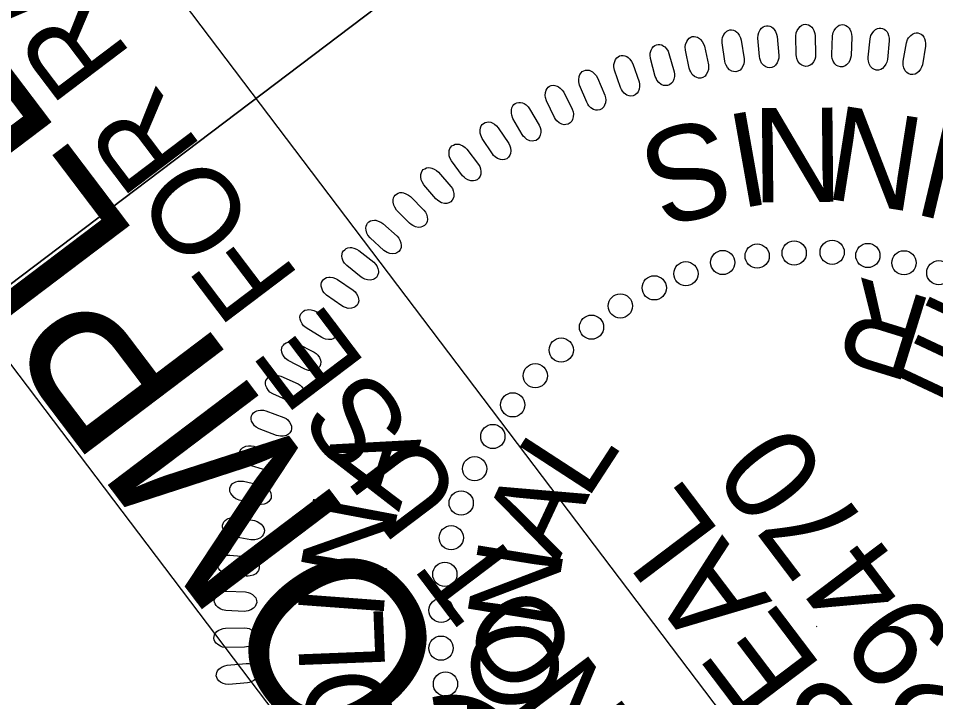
# Model space of a CAD drawing. Extents: x 475599 to 477488, y 499839 to 501843.
# Drawn here: x 475746.4 to 475807, y 501118.9 to 501163.8 of the extents above; entities that cross this region are included whole.
import ezdxf

# ---------------------------------------------------------------- set-up
doc = ezdxf.new("R2010")
doc.units = 0
for name, color, linetype in [('Sheet PE Seal Cell', 7, 'Continuous'), ('Sheet Plan CELL', 7, 'Continuous'), ('Sheet Sticker Exception Certification CELL', 7, 'Continuous'), ('Sheet Sticker Incomplete CELL', 7, 'Continuous')]:
    doc.layers.add(name, color=color, linetype=linetype)

msp = doc.modelspace()

# ---------------------------------------------------------------- linework, layer by layer
at = {"layer": 'Sheet PE Seal Cell'}
msp.add_line((475799.157, 501123.615), (475799.194, 501123.643), dxfattribs=at)
for points in [[(475795.387, 501161.299), (475795.286, 501162.522), (475795.305, 501162.744), (475795.345, 501162.887), (475795.443, 501163.065), (475795.531, 501163.183), (475795.637, 501163.272), (475795.738, 501163.319), (475795.848, 501163.348), (475795.961, 501163.338), (475796.083, 501163.318), (475796.192, 501163.267), (475796.304, 501163.176), (475796.371, 501163.102), (475796.45, 501162.957), (475796.524, 501162.784), (475796.56, 501162.627), (475796.67, 501161.375), (475796.661, 501161.204), (475796.628, 501161.061), (475796.552, 501160.895), (475796.452, 501160.746), (475796.362, 501160.659), (475796.21, 501160.587), (475796.062, 501160.554), (475795.911, 501160.582), (475795.802, 501160.623), (475795.667, 501160.712), (475795.534, 501160.871), (475795.452, 501161.045), (475795.412, 501161.171)], [(475797.815, 501161.431), (475797.791, 501162.657), (475797.825, 501162.877), (475797.874, 501163.018), (475797.983, 501163.19), (475798.078, 501163.301), (475798.189, 501163.384), (475798.292, 501163.425), (475798.404, 501163.447), (475798.516, 501163.429), (475798.637, 501163.402), (475798.742, 501163.345), (475798.848, 501163.246), (475798.91, 501163.168), (475798.981, 501163.019), (475799.044, 501162.841), (475799.07, 501162.682), (475799.101, 501161.426), (475799.082, 501161.256), (475799.039, 501161.116), (475798.953, 501160.954), (475798.844, 501160.812), (475798.748, 501160.731), (475798.592, 501160.668), (475798.443, 501160.645), (475798.293, 501160.682), (475798.187, 501160.73), (475798.058, 501160.827), (475797.935, 501160.994), (475797.865, 501161.173), (475797.833, 501161.301)], [(475800.162, 501161.446), (475800.216, 501162.671), (475800.262, 501162.888), (475800.32, 501163.026), (475800.44, 501163.191), (475800.542, 501163.296), (475800.658, 501163.371), (475800.764, 501163.406), (475800.877, 501163.421), (475800.987, 501163.396), (475801.106, 501163.361), (475801.208, 501163.297), (475801.308, 501163.192), (475801.364, 501163.11), (475801.425, 501162.958), (475801.477, 501162.776), (475801.492, 501162.616), (475801.445, 501161.36), (475801.415, 501161.191), (475801.364, 501161.054), (475801.268, 501160.899), (475801.15, 501160.764), (475801.049, 501160.688), (475800.89, 501160.635), (475800.739, 501160.623), (475800.592, 501160.669), (475800.49, 501160.723), (475800.367, 501160.828), (475800.255, 501161.002), (475800.195, 501161.185), (475800.171, 501161.315)], [(475802.568, 501161.267), (475802.699, 501162.487), (475802.759, 501162.702), (475802.826, 501162.835), (475802.956, 501162.992), (475803.064, 501163.09), (475803.184, 501163.158), (475803.292, 501163.186), (475803.406, 501163.194), (475803.515, 501163.163), (475803.631, 501163.119), (475803.728, 501163.05), (475803.822, 501162.939), (475803.873, 501162.854), (475803.924, 501162.697), (475803.964, 501162.513), (475803.97, 501162.352), (475803.844, 501161.102), (475803.803, 501160.935), (475803.743, 501160.801), (475803.638, 501160.652), (475803.512, 501160.525), (475803.406, 501160.456), (475803.244, 501160.413), (475803.093, 501160.41), (475802.949, 501160.465), (475802.85, 501160.526), (475802.734, 501160.638), (475802.634, 501160.819), (475802.585, 501161.006), (475802.569, 501161.137)], [(475790.751, 501160.531), (475790.498, 501161.732), (475790.49, 501161.954), (475790.511, 501162.101), (475790.586, 501162.291), (475790.659, 501162.418), (475790.752, 501162.519), (475790.846, 501162.58), (475790.952, 501162.622), (475791.065, 501162.626), (475791.189, 501162.621), (475791.303, 501162.585), (475791.426, 501162.508), (475791.501, 501162.443), (475791.598, 501162.31), (475791.693, 501162.147), (475791.748, 501161.995), (475792.015, 501160.767), (475792.028, 501160.597), (475792.013, 501160.451), (475791.958, 501160.276), (475791.877, 501160.117), (475791.799, 501160.019), (475791.657, 501159.928), (475791.515, 501159.877), (475791.361, 501159.885), (475791.248, 501159.913), (475791.103, 501159.984), (475790.951, 501160.125), (475790.848, 501160.287), (475790.792, 501160.407)], [(475793.096, 501160.991), (475792.919, 501162.205), (475792.925, 501162.427), (475792.956, 501162.574), (475793.042, 501162.758), (475793.123, 501162.88), (475793.222, 501162.975), (475793.32, 501163.03), (475793.428, 501163.066), (475793.542, 501163.063), (475793.665, 501163.05), (475793.776, 501163.006), (475793.895, 501162.922), (475793.965, 501162.852), (475794.054, 501162.714), (475794.138, 501162.544), (475794.184, 501162.391), (475794.373, 501161.148), (475794.375, 501160.977), (475794.351, 501160.832), (475794.285, 501160.662), (475794.195, 501160.507), (475794.11, 501160.414), (475793.964, 501160.332), (475793.818, 501160.291), (475793.664, 501160.309), (475793.554, 501160.343), (475793.413, 501160.423), (475793.271, 501160.573), (475793.178, 501160.742), (475793.13, 501160.865)], [(475804.892, 501161.004), (475805.099, 501162.214), (475805.172, 501162.424), (475805.248, 501162.553), (475805.386, 501162.701), (475805.501, 501162.793), (475805.625, 501162.852), (475805.735, 501162.874), (475805.849, 501162.875), (475805.956, 501162.836), (475806.068, 501162.787), (475806.162, 501162.711), (475806.248, 501162.594), (475806.294, 501162.505), (475806.335, 501162.347), (475806.364, 501162.159), (475806.359, 501161.999), (475806.154, 501160.759), (475806.104, 501160.595), (475806.035, 501160.465), (475805.921, 501160.323), (475805.787, 501160.204), (475805.677, 501160.142), (475805.513, 501160.109), (475805.362, 501160.115), (475805.222, 501160.18), (475805.127, 501160.246), (475805.018, 501160.366), (475804.929, 501160.553), (475804.892, 501160.742), (475804.885, 501160.874)], [(475788.506, 501159.989), (475788.178, 501161.171), (475788.156, 501161.392), (475788.168, 501161.541), (475788.231, 501161.734), (475788.296, 501161.866), (475788.382, 501161.973), (475788.473, 501162.039), (475788.575, 501162.088), (475788.688, 501162.099), (475788.812, 501162.102), (475788.928, 501162.073), (475789.056, 501162.004), (475789.135, 501161.943), (475789.24, 501161.817), (475789.346, 501161.66), (475789.41, 501161.513), (475789.753, 501160.304), (475789.776, 501160.134), (475789.771, 501159.988), (475789.726, 501159.81), (475789.656, 501159.646), (475789.584, 501159.542), (475789.449, 501159.443), (475789.31, 501159.384), (475789.155, 501159.382), (475789.041, 501159.403), (475788.892, 501159.464), (475788.732, 501159.596), (475788.618, 501159.751), (475788.555, 501159.868)], [(475786.206, 501159.252), (475785.804, 501160.412), (475785.768, 501160.631), (475785.771, 501160.781), (475785.822, 501160.978), (475785.878, 501161.113), (475785.958, 501161.225), (475786.044, 501161.297), (475786.143, 501161.352), (475786.255, 501161.37), (475786.379, 501161.381), (475786.497, 501161.359), (475786.628, 501161.299), (475786.711, 501161.243), (475786.823, 501161.123), (475786.939, 501160.974), (475787.013, 501160.83), (475787.43, 501159.645), (475787.464, 501159.478), (475787.468, 501159.331), (475787.436, 501159.151), (475787.375, 501158.982), (475787.31, 501158.875), (475787.181, 501158.767), (475787.045, 501158.699), (475786.892, 501158.688), (475786.777, 501158.701), (475786.624, 501158.753), (475786.456, 501158.875), (475786.333, 501159.023), (475786.263, 501159.135)], [(475783.974, 501158.281), (475783.5, 501159.413), (475783.45, 501159.629), (475783.444, 501159.778), (475783.482, 501159.978), (475783.529, 501160.116), (475783.603, 501160.234), (475783.683, 501160.31), (475783.779, 501160.372), (475783.89, 501160.397), (475784.012, 501160.416), (475784.132, 501160.401), (475784.267, 501160.349), (475784.353, 501160.299), (475784.473, 501160.187), (475784.597, 501160.044), (475784.679, 501159.906), (475785.171, 501158.75), (475785.216, 501158.584), (475785.228, 501158.438), (475785.208, 501158.257), (475785.157, 501158.085), (475785.099, 501157.974), (475784.977, 501157.857), (475784.847, 501157.781), (475784.694, 501157.76), (475784.578, 501157.766), (475784.422, 501157.809), (475784.246, 501157.919), (475784.114, 501158.059), (475784.038, 501158.167)], [(475781.85, 501157.277), (475781.307, 501158.376), (475781.243, 501158.589), (475781.227, 501158.738), (475781.253, 501158.94), (475781.292, 501159.081), (475781.356, 501159.203), (475781.433, 501159.284), (475781.524, 501159.352), (475781.634, 501159.384), (475781.754, 501159.41), (475781.875, 501159.403), (475782.013, 501159.359), (475782.102, 501159.315), (475782.228, 501159.211), (475782.361, 501159.076), (475782.452, 501158.943), (475783.016, 501157.82), (475783.071, 501157.658), (475783.092, 501157.513), (475783.082, 501157.33), (475783.044, 501157.155), (475782.992, 501157.041), (475782.878, 501156.917), (475782.753, 501156.833), (475782.601, 501156.803), (475782.485, 501156.801), (475782.327, 501156.834), (475782.145, 501156.933), (475782.005, 501157.065), (475781.921, 501157.167)], [(475779.707, 501156.152), (475779.095, 501157.216), (475779.019, 501157.425), (475778.994, 501157.572), (475779.006, 501157.775), (475779.036, 501157.919), (475779.094, 501158.043), (475779.164, 501158.13), (475779.252, 501158.203), (475779.359, 501158.242), (475779.478, 501158.275), (475779.598, 501158.276), (475779.738, 501158.242), (475779.83, 501158.203), (475779.963, 501158.106), (475780.104, 501157.98), (475780.203, 501157.853), (475780.836, 501156.767), (475780.902, 501156.609), (475780.932, 501156.466), (475780.934, 501156.283), (475780.906, 501156.106), (475780.862, 501155.988), (475780.755, 501155.858), (475780.636, 501155.767), (475780.486, 501155.727), (475780.371, 501155.718), (475780.211, 501155.74), (475780.023, 501155.828), (475779.875, 501155.95), (475779.785, 501156.048)], [(475777.741, 501154.873), (475777.063, 501155.896), (475776.974, 501156.099), (475776.94, 501156.245), (475776.94, 501156.449), (475776.961, 501156.594), (475777.01, 501156.721), (475777.075, 501156.812), (475777.158, 501156.891), (475777.262, 501156.936), (475777.378, 501156.978), (475777.499, 501156.986), (475777.641, 501156.96), (475777.735, 501156.926), (475777.874, 501156.839), (475778.023, 501156.722), (475778.13, 501156.601), (475778.829, 501155.558), (475778.904, 501155.404), (475778.944, 501155.263), (475778.957, 501155.08), (475778.94, 501154.902), (475778.904, 501154.782), (475778.806, 501154.645), (475778.692, 501154.546), (475778.545, 501154.497), (475778.431, 501154.481), (475778.27, 501154.494), (475778.077, 501154.569), (475777.921, 501154.682), (475777.825, 501154.773)], [(475775.775, 501153.426), (475775.035, 501154.405), (475774.933, 501154.602), (475774.89, 501154.745), (475774.877, 501154.948), (475774.888, 501155.094), (475774.93, 501155.226), (475774.989, 501155.32), (475775.067, 501155.404), (475775.168, 501155.456), (475775.281, 501155.504), (475775.401, 501155.519), (475775.544, 501155.503), (475775.64, 501155.475), (475775.784, 501155.397), (475775.94, 501155.29), (475776.054, 501155.176), (475776.819, 501154.178), (475776.903, 501154.03), (475776.951, 501153.891), (475776.976, 501153.709), (475776.971, 501153.531), (475776.942, 501153.408), (475776.852, 501153.266), (475776.745, 501153.16), (475776.602, 501153.102), (475776.488, 501153.079), (475776.327, 501153.081), (475776.129, 501153.145), (475775.967, 501153.247), (475775.865, 501153.332)], [(475774.007, 501151.901), (475773.207, 501152.831), (475773.093, 501153.022), (475773.041, 501153.161), (475773.015, 501153.364), (475773.017, 501153.51), (475773.051, 501153.644), (475773.104, 501153.742), (475773.176, 501153.83), (475773.274, 501153.888), (475773.384, 501153.944), (475773.502, 501153.967), (475773.646, 501153.959), (475773.744, 501153.937), (475773.893, 501153.868), (475774.055, 501153.771), (475774.176, 501153.665), (475775.001, 501152.717), (475775.095, 501152.574), (475775.151, 501152.438), (475775.188, 501152.259), (475775.194, 501152.08), (475775.172, 501151.956), (475775.092, 501151.809), (475774.992, 501151.696), (475774.853, 501151.629), (475774.74, 501151.598), (475774.579, 501151.591), (475774.378, 501151.642), (475774.21, 501151.734), (475774.103, 501151.813)], [(475772.268, 501150.28), (475771.412, 501151.158), (475771.285, 501151.341), (475771.225, 501151.477), (475771.187, 501151.677), (475771.179, 501151.823), (475771.204, 501151.959), (475771.251, 501152.06), (475771.317, 501152.152), (475771.411, 501152.217), (475771.518, 501152.279), (475771.635, 501152.31), (475771.779, 501152.311), (475771.877, 501152.296), (475772.031, 501152.235), (475772.199, 501152.149), (475772.327, 501152.051), (475773.21, 501151.156), (475773.311, 501151.019), (475773.377, 501150.888), (475773.424, 501150.711), (475773.442, 501150.533), (475773.428, 501150.408), (475773.358, 501150.255), (475773.264, 501150.137), (475773.129, 501150.061), (475773.02, 501150.024), (475772.859, 501150.006), (475772.655, 501150.044), (475772.482, 501150.126), (475772.37, 501150.198)], [(475770.564, 501148.49), (475769.654, 501149.312), (475769.516, 501149.487), (475769.447, 501149.62), (475769.397, 501149.817), (475769.38, 501149.962), (475769.396, 501150.099), (475769.437, 501150.203), (475769.497, 501150.3), (475769.587, 501150.369), (475769.69, 501150.438), (475769.804, 501150.476), (475769.948, 501150.487), (475770.047, 501150.478), (475770.204, 501150.427), (475770.377, 501150.351), (475770.51, 501150.261), (475771.448, 501149.424), (475771.559, 501149.293), (475771.632, 501149.167), (475771.69, 501148.993), (475771.719, 501148.817), (475771.713, 501148.691), (475771.652, 501148.534), (475771.566, 501148.41), (475771.437, 501148.326), (475771.33, 501148.282), (475771.17, 501148.254), (475770.965, 501148.279), (475770.785, 501148.35), (475770.67, 501148.415)], [(475769.074, 501146.723), (475768.114, 501147.487), (475767.966, 501147.652), (475767.889, 501147.78), (475767.825, 501147.974), (475767.8, 501148.118), (475767.808, 501148.255), (475767.842, 501148.362), (475767.896, 501148.462), (475767.981, 501148.538), (475768.079, 501148.613), (475768.19, 501148.657), (475768.334, 501148.677), (475768.434, 501148.675), (475768.593, 501148.634), (475768.771, 501148.569), (475768.91, 501148.487), (475769.897, 501147.711), (475770.016, 501147.588), (475770.098, 501147.466), (475770.167, 501147.296), (475770.206, 501147.122), (475770.208, 501146.996), (475770.157, 501146.836), (475770.08, 501146.706), (475769.955, 501146.615), (475769.852, 501146.564), (475769.694, 501146.526), (475769.488, 501146.538), (475769.305, 501146.597), (475769.185, 501146.655)], [(475767.791, 501144.818), (475766.784, 501145.52), (475766.626, 501145.676), (475766.541, 501145.799), (475766.467, 501145.988), (475766.432, 501146.13), (475766.431, 501146.268), (475766.458, 501146.376), (475766.506, 501146.48), (475766.586, 501146.56), (475766.679, 501146.641), (475766.788, 501146.693), (475766.93, 501146.721), (475767.029, 501146.725), (475767.191, 501146.695), (475767.372, 501146.641), (475767.516, 501146.568), (475768.551, 501145.856), (475768.677, 501145.74), (475768.765, 501145.623), (475768.845, 501145.459), (475768.896, 501145.287), (475768.906, 501145.161), (475768.865, 501144.998), (475768.796, 501144.864), (475768.677, 501144.764), (475768.577, 501144.707), (475768.422, 501144.66), (475768.215, 501144.659), (475768.029, 501144.706), (475767.906, 501144.756)], [(475766.473, 501142.724), (475765.425, 501143.361), (475765.257, 501143.508), (475765.165, 501143.624), (475765.078, 501143.808), (475765.035, 501143.948), (475765.025, 501144.086), (475765.045, 501144.196), (475765.086, 501144.302), (475765.162, 501144.387), (475765.25, 501144.474), (475765.354, 501144.532), (475765.495, 501144.57), (475765.594, 501144.58), (475765.757, 501144.56), (475765.941, 501144.518), (475766.089, 501144.454), (475767.167, 501143.807), (475767.3, 501143.7), (475767.396, 501143.589), (475767.486, 501143.43), (475767.547, 501143.262), (475767.565, 501143.136), (475767.534, 501142.971), (475767.473, 501142.833), (475767.362, 501142.726), (475767.264, 501142.663), (475767.113, 501142.606), (475766.906, 501142.592), (475766.718, 501142.628), (475766.592, 501142.67)], [(475765.341, 501140.639), (475764.255, 501141.209), (475764.078, 501141.344), (475763.978, 501141.455), (475763.881, 501141.633), (475763.829, 501141.77), (475763.81, 501141.907), (475763.824, 501142.018), (475763.858, 501142.127), (475763.928, 501142.217), (475764.01, 501142.308), (475764.111, 501142.373), (475764.249, 501142.42), (475764.347, 501142.436), (475764.511, 501142.426), (475764.697, 501142.395), (475764.849, 501142.34), (475765.965, 501141.763), (475766.105, 501141.664), (475766.208, 501141.56), (475766.307, 501141.407), (475766.379, 501141.242), (475766.404, 501141.119), (475766.384, 501140.952), (475766.332, 501140.81), (475766.228, 501140.697), (475766.135, 501140.627), (475765.987, 501140.561), (475765.782, 501140.534), (475765.591, 501140.558), (475765.463, 501140.592)], [(475764.349, 501138.499), (475763.229, 501139), (475763.044, 501139.124), (475762.938, 501139.227), (475762.828, 501139.399), (475762.768, 501139.533), (475762.741, 501139.668), (475762.748, 501139.78), (475762.775, 501139.89), (475762.839, 501139.984), (475762.915, 501140.081), (475763.012, 501140.153), (475763.146, 501140.208), (475763.243, 501140.229), (475763.408, 501140.23), (475763.596, 501140.211), (475763.751, 501140.166), (475764.901, 501139.66), (475765.046, 501139.57), (475765.156, 501139.472), (475765.264, 501139.325), (475765.346, 501139.167), (475765.38, 501139.045), (475765.37, 501138.877), (475765.327, 501138.732), (475765.23, 501138.612), (475765.142, 501138.537), (475764.998, 501138.462), (475764.795, 501138.422), (475764.603, 501138.434), (475764.473, 501138.459)], [(475763.475, 501136.256), (475762.326, 501136.685), (475762.133, 501136.798), (475762.021, 501136.895), (475761.901, 501137.059), (475761.833, 501137.189), (475761.797, 501137.322), (475761.797, 501137.434), (475761.817, 501137.546), (475761.875, 501137.644), (475761.945, 501137.746), (475762.038, 501137.823), (475762.168, 501137.886), (475762.263, 501137.914), (475762.428, 501137.925), (475762.616, 501137.918), (475762.773, 501137.883), (475763.953, 501137.45), (475764.104, 501137.37), (475764.219, 501137.278), (475764.337, 501137.139), (475764.429, 501136.985), (475764.47, 501136.866), (475764.471, 501136.698), (475764.437, 501136.551), (475764.347, 501136.425), (475764.264, 501136.344), (475764.126, 501136.26), (475763.926, 501136.207), (475763.733, 501136.207), (475763.602, 501136.225)], [(475762.769, 501133.965), (475761.595, 501134.322), (475761.396, 501134.421), (475761.278, 501134.511), (475761.148, 501134.668), (475761.071, 501134.793), (475761.028, 501134.923), (475761.02, 501135.035), (475761.033, 501135.149), (475761.085, 501135.25), (475761.148, 501135.355), (475761.236, 501135.438), (475761.362, 501135.509), (475761.456, 501135.544), (475761.619, 501135.564), (475761.807, 501135.569), (475761.967, 501135.545), (475763.171, 501135.187), (475763.326, 501135.116), (475763.448, 501135.032), (475763.574, 501134.9), (475763.675, 501134.752), (475763.723, 501134.636), (475763.735, 501134.468), (475763.711, 501134.319), (475763.629, 501134.188), (475763.551, 501134.103), (475763.418, 501134.01), (475763.221, 501133.945), (475763.03, 501133.932), (475762.897, 501133.942)], [(475762.197, 501131.701), (475761.003, 501131.983), (475760.798, 501132.07), (475760.674, 501132.153), (475760.535, 501132.301), (475760.451, 501132.421), (475760.399, 501132.548), (475760.384, 501132.659), (475760.39, 501132.773), (475760.436, 501132.877), (475760.493, 501132.987), (475760.575, 501133.075), (475760.696, 501133.154), (475760.787, 501133.194), (475760.949, 501133.225), (475761.137, 501133.241), (475761.297, 501133.227), (475762.522, 501132.945), (475762.682, 501132.884), (475762.807, 501132.808), (475762.942, 501132.684), (475763.052, 501132.543), (475763.108, 501132.43), (475763.13, 501132.264), (475763.114, 501132.114), (475763.041, 501131.978), (475762.969, 501131.887), (475762.843, 501131.786), (475762.65, 501131.709), (475762.46, 501131.685), (475762.327, 501131.686)], [(475761.778, 501129.361), (475760.568, 501129.568), (475760.359, 501129.642), (475760.229, 501129.717), (475760.081, 501129.856), (475759.99, 501129.97), (475759.93, 501130.094), (475759.908, 501130.204), (475759.907, 501130.318), (475759.946, 501130.425), (475759.996, 501130.538), (475760.072, 501130.631), (475760.188, 501130.718), (475760.277, 501130.763), (475760.436, 501130.804), (475760.622, 501130.833), (475760.784, 501130.828), (475762.024, 501130.623), (475762.187, 501130.573), (475762.317, 501130.505), (475762.459, 501130.39), (475762.578, 501130.256), (475762.641, 501130.147), (475762.673, 501129.982), (475762.667, 501129.831), (475762.603, 501129.69), (475762.536, 501129.596), (475762.416, 501129.487), (475762.229, 501129.398), (475762.04, 501129.362), (475761.908, 501129.354)], [(475761.48, 501126.948), (475760.26, 501127.079), (475760.046, 501127.139), (475759.913, 501127.206), (475759.756, 501127.335), (475759.657, 501127.444), (475759.59, 501127.564), (475759.561, 501127.672), (475759.553, 501127.786), (475759.585, 501127.895), (475759.628, 501128.011), (475759.698, 501128.108), (475759.808, 501128.202), (475759.894, 501128.253), (475760.05, 501128.304), (475760.235, 501128.344), (475760.396, 501128.35), (475761.646, 501128.224), (475761.812, 501128.183), (475761.946, 501128.124), (475762.095, 501128.018), (475762.222, 501127.892), (475762.292, 501127.786), (475762.335, 501127.624), (475762.339, 501127.473), (475762.282, 501127.329), (475762.222, 501127.23), (475762.11, 501127.114), (475761.928, 501127.013), (475761.743, 501126.966), (475761.61, 501126.95)], [(475761.342, 501124.622), (475760.117, 501124.676), (475759.899, 501124.722), (475759.762, 501124.781), (475759.597, 501124.9), (475759.492, 501125.002), (475759.417, 501125.117), (475759.382, 501125.223), (475759.367, 501125.337), (475759.391, 501125.447), (475759.427, 501125.566), (475759.491, 501125.668), (475759.595, 501125.768), (475759.677, 501125.825), (475759.83, 501125.885), (475760.012, 501125.937), (475760.172, 501125.953), (475761.428, 501125.905), (475761.597, 501125.876), (475761.734, 501125.824), (475761.889, 501125.728), (475762.024, 501125.61), (475762.1, 501125.509), (475762.153, 501125.35), (475762.166, 501125.2), (475762.12, 501125.052), (475762.065, 501124.95), (475761.96, 501124.827), (475761.786, 501124.716), (475761.603, 501124.656), (475761.472, 501124.632)], [(475761.356, 501122.257), (475760.13, 501122.233), (475759.91, 501122.266), (475759.769, 501122.316), (475759.597, 501122.425), (475759.486, 501122.52), (475759.404, 501122.63), (475759.362, 501122.734), (475759.34, 501122.846), (475759.357, 501122.958), (475759.385, 501123.078), (475759.443, 501123.184), (475759.541, 501123.291), (475759.619, 501123.353), (475759.768, 501123.423), (475759.946, 501123.486), (475760.105, 501123.511), (475761.361, 501123.543), (475761.531, 501123.523), (475761.672, 501123.481), (475761.833, 501123.395), (475761.975, 501123.286), (475762.057, 501123.19), (475762.119, 501123.034), (475762.142, 501122.885), (475762.105, 501122.735), (475762.057, 501122.629), (475761.96, 501122.5), (475761.793, 501122.377), (475761.615, 501122.307), (475761.485, 501122.274)], [(475761.548, 501119.894), (475760.326, 501119.793), (475760.104, 501119.812), (475759.961, 501119.853), (475759.782, 501119.951), (475759.665, 501120.039), (475759.576, 501120.144), (475759.528, 501120.245), (475759.499, 501120.356), (475759.509, 501120.469), (475759.53, 501120.59), (475759.58, 501120.7), (475759.672, 501120.812), (475759.746, 501120.878), (475759.89, 501120.958), (475760.064, 501121.032), (475760.221, 501121.067), (475761.473, 501121.178), (475761.643, 501121.169), (475761.786, 501121.136), (475761.953, 501121.06), (475762.101, 501120.96), (475762.189, 501120.869), (475762.261, 501120.718), (475762.293, 501120.57), (475762.266, 501120.418), (475762.224, 501120.309), (475762.136, 501120.174), (475761.977, 501120.042), (475761.803, 501119.96), (475761.676, 501119.92)]]:
    msp.add_lwpolyline(points, close=True, dxfattribs=at)
for centre in [(475795.238, 501148.114), (475797.683, 501148.316), (475800.192, 501148.367), (475802.55, 501148.154), (475792.961, 501147.69), (475804.943, 501147.671), (475790.527, 501146.947), (475807.239, 501147.012), (475788.435, 501146.014), (475786.193, 501144.817), (475784.291, 501143.414), (475782.289, 501141.9), (475780.575, 501140.204), (475779.085, 501138.278), (475777.77, 501136.186), (475776.564, 501134.053), (475775.68, 501131.787), (475775.02, 501129.491), (475774.599, 501127.075), (475774.353, 501124.693), (475774.347, 501122.192), (475774.642, 501119.82)]:
    msp.add_circle(centre, 0.801, dxfattribs=at)
at = {"layer": 'Sheet Plan CELL'}
msp.add_line((475717.254, 501124.582), (475806.917, 501192.468), dxfattribs=at)
for points in [[(475717.254, 501124.582), (475656.898, 501204.298), (475746.601, 501272.214), (475806.965, 501192.488)], [(475777.638, 501044.809), (475717.254, 501124.582), (475806.965, 501192.488), (475867.321, 501112.709)]]:
    msp.add_lwpolyline(points, close=True, dxfattribs=at)
at = {"layer": 'Sheet Sticker Incomplete CELL'}
msp.add_lwpolyline([(475806.465, 501099.927), (475787.727, 501085.744), (475699.007, 501202.952), (475717.745, 501217.135)], close=True, dxfattribs=at)

# ---------------------------------------------------------------- texts
at = {"layer": 'Sheet PE Seal Cell'}
for s, height, rotation, p in [('N', 6.236, 180.53581, (475800.891, 501157.945)), ('N', 6.236, 171.04613, (475806.511, 501157.171)), ('S', 6.236, 194.45311, (475792.6, 501157.385)), ('I', 6.236, 190.0255, (475795.22, 501157.782)), ('I', 6.236, 166.61851, (475809.072, 501156.494)), ('R', 5.669, 162.7872, (475806.996, 501145.185)), ('E', 5.669, 154.8474, (475810.922, 501143.415)), ('A', 5.669, 72.79646, (475771.569, 501131.166)), ('L', 5.669, 56.95449, (475783.968, 501131.908)), ('29470', 6.2363, 127.105, (475811.214, 501118.929)), ('A', 5.669, 64.89429, (475782.065, 501127.804)), ('SEAL', 6.2363, 127.105, (475802.979, 501116.422)), ('N', 5.669, 79.28582, (475770.559, 501126.238)), ('N', 5.669, 80.77388, (475781.623, 501123.283)), ('I', 5.669, 85.77517, (475770.516, 501123.941)), ('L', 5.669, 92.26453, (475770.664, 501120.676)), ('O', 5.669, 96.65348, (475782.388, 501118.455)), ('O', 5.669, 98.75389, (475771.502, 501115.374))]:
    msp.add_text(s, height=height, rotation=rotation, dxfattribs=at).set_placement(p)
at = {"layer": 'Sheet Sticker Exception Certification CELL'}
for s, p in [('UNLESS ALL SIGNATURES COMPLETED', (475872.93, 501137.021)), ('UNLESS ALL SIGNATURES COMPLETED', (475872.93, 501137.021)), ('DOCUMENT NOT CONSIDERED FINAL', (475862.853, 501135.754)), ('DOCUMENT NOT CONSIDERED FINAL', (475862.853, 501135.754))]:
    msp.add_text(s, height=5.5, rotation=127.12364, dxfattribs=at).set_placement(p)
at = {"layer": 'Sheet Sticker Incomplete CELL'}
for s, height, p in [('INCOMPLETE PLANS', 11.52, (475791.734, 501100.002)), ('DO NOT USE FOR R/W ACQUISITION', 5.76, (475795.314, 501106.788))]:
    msp.add_text(s, height=height, rotation=127.12364, dxfattribs=at).set_placement(p)

doc.saveas('drawing.dxf')
